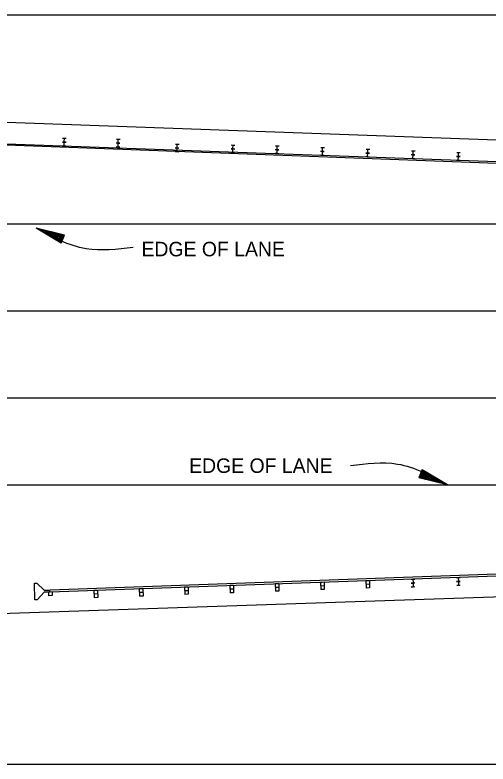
# Model space of a CAD drawing. Extents: x 1405295 to 1406670, y 2087573 to 2090763.
# Drawn here: x 1405823.7 to 1406019.3, y 2087970.1 to 2088280.1 of the extents above; entities that cross this region are included whole.
import ezdxf

# ---------------------------------------------------------------- set-up
doc = ezdxf.new("R2010")
doc.units = 0
doc.layers.add('22', color=7, linetype='Continuous')
doc.layers.add('Default', color=7, linetype='Continuous')

msp = doc.modelspace()

# ---------------------------------------------------------------- linework, layer by layer
at = {"layer": '22'}
for points in [[(1405649.36, 2088280.09), (1406363.11, 2088280.09), (1406363.11, 2088221.33)], [(1405758.1, 2087970.09), (1406363.11, 2087970.09), (1406363.11, 2088042.57)]]:
    msp.add_lwpolyline(points, dxfattribs=at)
at = {"layer": 'Default'}
for p, q in [((1406213.47, 2088221.32), (1405733.89, 2088238.72)), ((1406213.1, 2088211.57), (1405771.29, 2088228.01)), ((1406213.14, 2088212.38), (1405771.3, 2088228.41)), ((1405843.34, 2088227.61), (1405844.09, 2088227.6)), ((1405843.34, 2088227.49), (1405844.09, 2088227.48)), ((1405843.4, 2088229.11), (1405844.15, 2088229.1)), ((1405844.04, 2088225.98), (1405844.09, 2088227.48)), ((1405844.09, 2088227.6), (1405844.15, 2088229.1)), ((1405844.09, 2088227.6), (1405844.84, 2088227.56)), ((1405844.09, 2088227.48), (1405844.84, 2088227.44)), ((1405844.15, 2088229.1), (1405844.9, 2088229.07)), ((1405865.63, 2088227.11), (1405866.38, 2088227.09)), ((1405865.64, 2088227.23), (1405866.39, 2088227.21)), ((1405865.69, 2088228.72), (1405866.44, 2088228.71)), ((1405866.33, 2088225.59), (1405866.38, 2088227.09)), ((1405866.38, 2088227.09), (1405867.13, 2088227.05)), ((1405866.39, 2088227.21), (1405866.44, 2088228.71)), ((1405866.39, 2088227.21), (1405867.14, 2088227.17)), ((1405866.44, 2088228.71), (1405867.19, 2088228.68)), ((1405890.05, 2088226.69), (1405890.8, 2088226.67)), ((1405890.75, 2088225.17), (1405890.8, 2088226.67)), ((1405890.8, 2088226.67), (1405891.55, 2088226.64)), ((1405843.29, 2088225.99), (1405844.04, 2088225.98)), ((1405844.04, 2088225.98), (1405844.79, 2088225.95)), ((1405865.58, 2088225.61), (1405866.33, 2088225.59)), ((1405866.33, 2088225.59), (1405867.08, 2088225.56)), ((1405889.94, 2088223.57), (1405890.69, 2088223.55)), ((1405890, 2088225.19), (1405890.75, 2088225.17)), ((1405890, 2088225.07), (1405890.75, 2088225.05)), ((1405890.69, 2088223.55), (1405890.75, 2088225.05)), ((1405890.69, 2088223.55), (1405891.44, 2088223.52)), ((1405890.75, 2088225.17), (1405891.5, 2088225.13)), ((1405890.75, 2088225.05), (1405891.5, 2088225.01)), ((1405913.1, 2088224.79), (1405913.85, 2088224.77)), ((1405913.1, 2088224.67), (1405913.85, 2088224.65)), ((1405913.15, 2088226.29), (1405913.9, 2088226.27)), ((1405913.79, 2088223.15), (1405913.85, 2088224.65)), ((1405913.85, 2088224.77), (1405913.9, 2088226.27)), ((1405913.85, 2088224.77), (1405914.6, 2088224.73)), ((1405913.85, 2088224.65), (1405914.59, 2088224.61)), ((1405913.9, 2088226.27), (1405914.65, 2088226.24)), ((1405931.37, 2088224.35), (1405932.12, 2088224.34)), ((1405931.38, 2088224.47), (1405932.13, 2088224.46)), ((1405931.43, 2088225.97), (1405932.18, 2088225.96)), ((1405932.07, 2088222.84), (1405932.12, 2088224.34)), ((1405932.12, 2088224.34), (1405932.87, 2088224.29)), ((1405932.13, 2088224.46), (1405932.18, 2088225.96)), ((1405932.13, 2088224.46), (1405932.88, 2088224.41)), ((1405932.18, 2088225.96), (1405932.93, 2088225.92)), ((1405950.12, 2088223.79), (1405950.87, 2088223.75)), ((1405950.12, 2088223.67), (1405950.87, 2088223.63)), ((1405950.18, 2088225.29), (1405950.92, 2088225.25)), ((1405950.81, 2088222.13), (1405950.87, 2088223.63)), ((1405950.87, 2088223.75), (1405950.92, 2088225.25)), ((1405950.87, 2088223.75), (1405951.62, 2088223.73)), ((1405950.87, 2088223.63), (1405951.62, 2088223.61)), ((1405950.92, 2088225.25), (1405951.67, 2088225.23)), ((1405968.92, 2088224.59), (1405969.67, 2088224.57)), ((1405969.61, 2088223.06), (1405969.67, 2088224.57)), ((1405969.67, 2088224.57), (1405970.42, 2088224.52)), ((1405987.63, 2088223.9), (1405988.41, 2088223.85)), ((1405988.32, 2088222.35), (1405988.41, 2088223.85)), ((1405988.41, 2088223.85), (1405989.13, 2088223.84)), ((1405913.04, 2088223.17), (1405913.79, 2088223.15)), ((1405913.79, 2088223.15), (1405914.54, 2088223.12)), ((1405931.32, 2088222.85), (1405932.07, 2088222.84)), ((1405932.07, 2088222.84), (1405932.82, 2088222.81)), ((1405950.06, 2088222.17), (1405950.81, 2088222.13)), ((1405950.81, 2088222.13), (1405951.56, 2088222.11)), ((1405968.8, 2088221.47), (1405969.52, 2088221.46)), ((1405968.83, 2088222.96), (1405969.61, 2088222.94)), ((1405968.86, 2088223.08), (1405969.61, 2088223.06)), ((1405969.52, 2088221.46), (1405969.61, 2088222.94)), ((1405969.52, 2088221.46), (1405970.3, 2088221.4)), ((1405969.61, 2088223.06), (1405970.36, 2088223.02)), ((1405969.61, 2088222.94), (1405970.33, 2088222.9)), ((1405987.52, 2088220.78), (1405988.27, 2088220.73)), ((1405987.57, 2088222.28), (1405988.32, 2088222.23)), ((1405987.6, 2088222.4), (1405988.32, 2088222.35)), ((1405988.27, 2088220.73), (1405988.32, 2088222.23)), ((1405988.27, 2088220.73), (1405989.02, 2088220.72)), ((1405988.32, 2088222.35), (1405989.1, 2088222.34)), ((1405988.32, 2088222.23), (1405989.07, 2088222.22)), ((1406006.31, 2088221.57), (1406007.06, 2088221.55)), ((1406006.32, 2088221.69), (1406007.07, 2088221.67)), ((1406006.37, 2088223.18), (1406007.12, 2088223.17)), ((1406007.01, 2088220.05), (1406007.06, 2088221.55)), ((1406007.06, 2088221.55), (1406007.81, 2088221.52)), ((1406007.07, 2088221.67), (1406007.12, 2088223.17)), ((1406007.07, 2088221.67), (1406007.81, 2088221.63)), ((1406007.12, 2088223.17), (1406007.87, 2088223.13)), ((1406006.26, 2088220.07), (1406007.01, 2088220.05)), ((1406007.01, 2088220.05), (1406007.76, 2088220.01)), ((1406442.16, 2088193.52), (1405372.03, 2088193.52)), ((1405842.87, 2088185.6), (1405832.46, 2088191.84)), ((1405844.25, 2088188.93), (1405832.46, 2088191.84)), ((1405842.99, 2088185.87), (1405834.32, 2088191.07)), ((1405844.13, 2088188.67), (1405834.32, 2088191.07)), ((1405844.01, 2088188.36), (1405836.24, 2088190.28)), ((1405843.11, 2088186.17), (1405836.24, 2088190.28)), ((1405843.23, 2088186.44), (1405838.07, 2088189.53)), ((1405843.92, 2088188.09), (1405838.07, 2088189.53)), ((1405843.8, 2088187.82), (1405839.96, 2088188.75)), ((1405843.35, 2088186.75), (1405839.96, 2088188.75)), ((1405843.68, 2088187.52), (1405841.82, 2088188)), ((1405843.47, 2088187.01), (1405841.82, 2088188)), ((1405842.87, 2088185.6), (1405844.25, 2088188.93)), ((1406442.16, 2088157.51), (1405373.91, 2088157.51)), ((1406442.16, 2088121.51), (1405373.91, 2088121.51)), ((1405992.13, 2088091.96), (1405990.75, 2088088.63)), ((1405991.56, 2088090.55), (1405993.21, 2088089.56)), ((1405991.68, 2088090.82), (1405995.04, 2088088.82)), ((1405991.8, 2088091.12), (1405996.93, 2088088.03)), ((1405991.89, 2088091.39), (1405998.79, 2088087.28)), ((1405992.01, 2088091.7), (1406000.68, 2088086.47)), ((1405992.13, 2088091.96), (1406002.54, 2088085.72)), ((1405990.75, 2088088.63), (1406002.54, 2088085.72)), ((1405990.87, 2088088.9), (1406000.68, 2088086.47)), ((1405990.99, 2088089.2), (1405998.79, 2088087.28)), ((1405991.11, 2088089.47), (1405996.93, 2088088.03)), ((1405991.23, 2088089.74), (1405995.04, 2088088.82)), ((1405991.35, 2088090.04), (1405993.21, 2088089.56)), ((1406444.65, 2088085.51), (1405372.03, 2088085.51)), ((1406213.1, 2088055.51), (1405838.31, 2088042.02)), ((1406213.14, 2088054.7), (1405838.34, 2088041.21)), ((1406006.25, 2088047.25), (1406007, 2088047.29)), ((1406007, 2088047.29), (1406007.75, 2088047.3)), ((1406007, 2088047.29), (1406007.05, 2088045.79)), ((1405913.28, 2088043.96), (1405912.53, 2088043.91)), ((1405912.53, 2088043.91), (1405912.64, 2088040.91)), ((1405914.03, 2088043.98), (1405913.28, 2088043.96)), ((1405914.03, 2088043.98), (1405914.14, 2088040.97)), ((1405932.02, 2088044.61), (1405931.27, 2088044.6)), ((1405931.27, 2088044.6), (1405931.38, 2088041.61)), ((1405932.77, 2088044.62), (1405932.02, 2088044.61)), ((1405932.77, 2088044.62), (1405932.88, 2088041.64)), ((1405950.77, 2088045.28), (1405950.02, 2088045.27)), ((1405950.02, 2088045.27), (1405950.13, 2088042.26)), ((1405951.57, 2088043.82), (1405950.07, 2088043.76)), ((1405951.52, 2088045.31), (1405950.77, 2088045.28)), ((1405951.52, 2088045.31), (1405951.63, 2088042.32)), ((1405969.51, 2088045.96), (1405968.76, 2088045.92)), ((1405968.76, 2088045.92), (1405968.87, 2088042.93)), ((1405970.31, 2088044.47), (1405968.81, 2088044.42)), ((1405970.26, 2088045.97), (1405969.51, 2088045.96)), ((1405970.26, 2088045.97), (1405970.37, 2088042.98)), ((1405987.5, 2088046.59), (1405988.25, 2088046.6)), ((1405987.56, 2088045.09), (1405988.31, 2088045.1)), ((1405987.59, 2088044.97), (1405988.31, 2088044.98)), ((1405988.25, 2088046.6), (1405989, 2088046.64)), ((1405988.25, 2088046.6), (1405988.31, 2088045.1)), ((1405988.31, 2088045.1), (1405989.06, 2088045.15)), ((1405988.31, 2088044.98), (1405989.09, 2088045.03)), ((1405988.31, 2088044.98), (1405988.39, 2088043.48)), ((1406006.3, 2088045.75), (1406007.05, 2088045.79)), ((1406006.3, 2088045.63), (1406007.05, 2088045.68)), ((1406006.36, 2088044.13), (1406007.11, 2088044.17)), ((1406007.05, 2088045.79), (1406007.8, 2088045.8)), ((1406007.05, 2088045.68), (1406007.8, 2088045.69)), ((1406007.05, 2088045.68), (1406007.11, 2088044.17)), ((1406007.11, 2088044.17), (1406007.86, 2088044.18)), ((1405837.59, 2088041.21), (1405837.64, 2088039.71)), ((1405839.09, 2088041.27), (1405839.14, 2088039.77)), ((1405857.08, 2088041.92), (1405856.33, 2088041.9)), ((1405856.33, 2088041.9), (1405856.44, 2088038.9)), ((1405857.83, 2088041.96), (1405857.08, 2088041.92)), ((1405857.83, 2088041.96), (1405857.94, 2088038.96)), ((1405875.83, 2088042.6), (1405875.08, 2088042.56)), ((1405875.08, 2088042.56), (1405875.18, 2088039.56)), ((1405876.63, 2088041.12), (1405875.13, 2088041.06)), ((1405876.58, 2088042.62), (1405875.83, 2088042.6)), ((1405876.58, 2088042.62), (1405876.68, 2088039.62)), ((1405894.57, 2088043.26), (1405893.79, 2088043.25)), ((1405893.79, 2088043.25), (1405893.9, 2088040.25)), ((1405895.37, 2088041.81), (1405893.87, 2088041.75)), ((1405895.29, 2088043.31), (1405894.57, 2088043.26)), ((1405895.29, 2088043.31), (1405895.4, 2088040.32)), ((1405914.09, 2088042.47), (1405912.59, 2088042.41)), ((1405914.14, 2088040.97), (1405912.64, 2088040.91)), ((1405932.83, 2088043.13), (1405931.33, 2088043.1)), ((1405932.88, 2088041.64), (1405931.38, 2088041.61)), ((1405951.63, 2088042.32), (1405950.13, 2088042.26)), ((1405970.37, 2088042.98), (1405968.87, 2088042.93)), ((1405987.61, 2088043.47), (1405988.39, 2088043.48)), ((1405988.39, 2088043.48), (1405989.11, 2088043.53)), ((1405839.14, 2088039.77), (1405837.64, 2088039.71)), ((1405857.89, 2088040.46), (1405856.39, 2088040.41)), ((1405857.94, 2088038.96), (1405856.44, 2088038.9)), ((1405876.68, 2088039.62), (1405875.18, 2088039.56)), ((1405895.4, 2088040.32), (1405893.9, 2088040.25))]:
    msp.add_line(p, q, dxfattribs=at)
msp.add_lwpolyline([(1406213.26, 2088045.69), (1405809.19, 2088031.96)], dxfattribs=at)
msp.add_lwpolyline([(1405835.79, 2088041.99), (1405838.04, 2088042.01), (1405838.02, 2088041.21), (1405835.77, 2088041.18), (1405832.9, 2088038.06), (1405831.91, 2088038.07), (1405831.8, 2088045), (1405832.79, 2088044.99)], close=True, dxfattribs=at)
for points in [[(1405872.57, 2088183.91), (1405853.13, 2088183.31), (1405832.46, 2088191.84)], [(1405962.43, 2088093.64), (1405981.87, 2088094.24), (1406002.54, 2088085.72)]]:
    msp.add_spline(points, degree=3, dxfattribs=at)

# ---------------------------------------------------------------- texts
for p in [(1405876.03, 2088180.21), (1405895.74, 2088090.57)]:
    msp.add_text('EDGE OF LANE', height=6, rotation=360, dxfattribs=at).set_placement(p)

doc.saveas('drawing.dxf')
